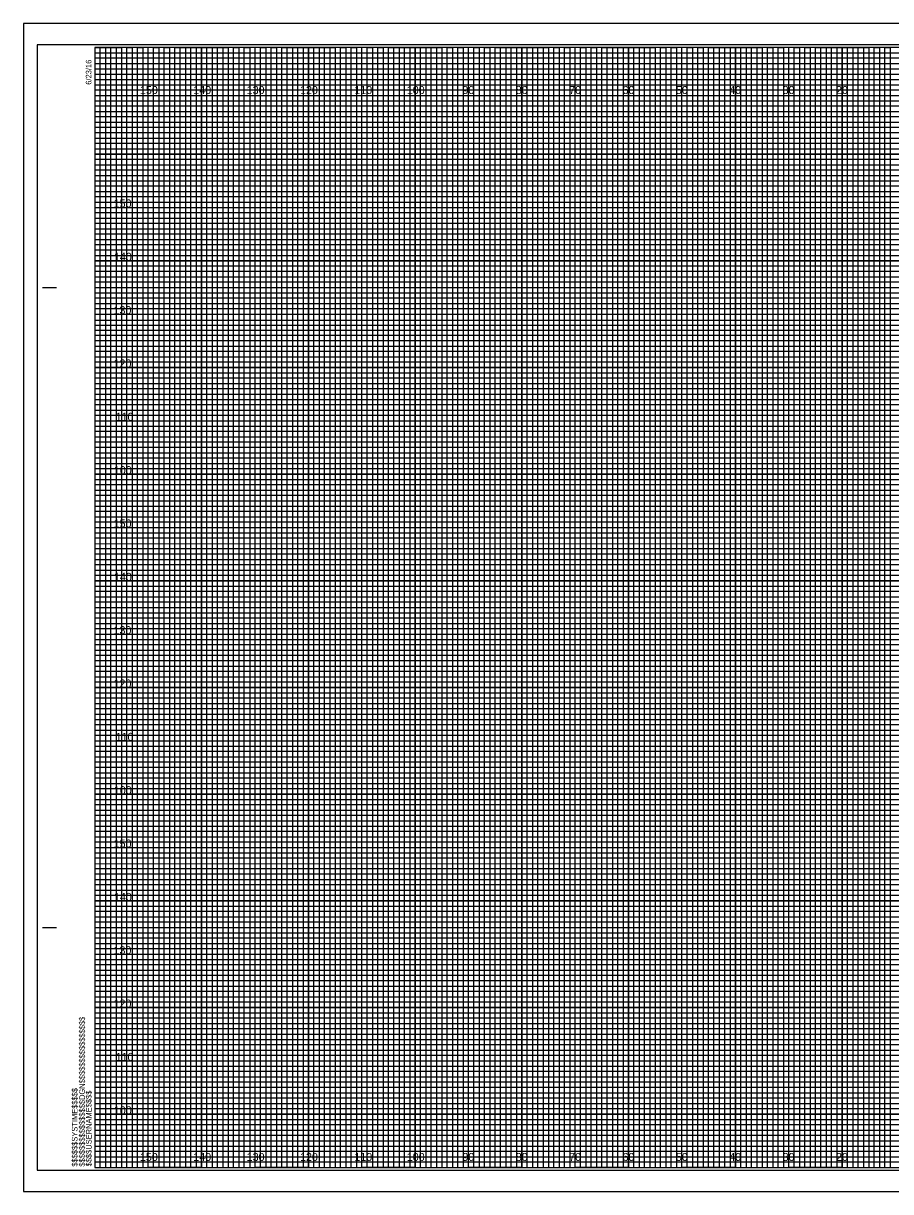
# Model space of a CAD drawing. Extents: x -13 to 323, y -5 to 2634.
# Drawn here: x -13.4 to 149.1, y 1755.5 to 1974.5 of the extents above; entities that cross this region are included whole.
import ezdxf

# ---------------------------------------------------------------- set-up
doc = ezdxf.new("R2010")
doc.units = 0
for name, color, linetype in [('Exist Cross Section Cell', 7, 'Continuous'), ('Exist XS Center Line Elevation Label', 7, 'Continuous'), ('Exist XS Ground Line', 7, 'Continuous'), ('Prop CMT Pvmt Course 1 Wedge', 7, 'Continuous'), ('Prop CMT Pvmt Course 2', 7, 'Continuous'), ('Prop CMT Pvmt Course 2 Wedge', 7, 'Continuous'), ('Prop CMT Pvmt Course 3', 7, 'Continuous'), ('Prop CMT Shld Paved Course 1', 7, 'Continuous'), ('Prop CMT Shld Paved Course 2', 7, 'Continuous'), ('Prop CMT Subgrade Earthwork', 7, 'Continuous'), ('Scratch_Level_0', 7, 'Continuous')]:
    doc.layers.add(name, color=color, linetype=linetype)

msp = doc.modelspace()

# ---------------------------------------------------------------- linework, layer by layer
at = {"layer": 'Exist XS Center Line Elevation Label'}
for points in [[(0, 1970), (5, 1970), (5, 1760), (15, 1760), (15, 1970), (25, 1970), (25, 1760), (35, 1760), (35, 1970), (45, 1970), (45, 1760), (55, 1760), (55, 1970), (65, 1970), (65, 1760), (75, 1760), (75, 1970), (85, 1970), (85, 1760), (95, 1760), (95, 1970), (105, 1970), (105, 1760), (115, 1760), (115, 1970), (125, 1970), (125, 1760), (135, 1760), (135, 1970), (145, 1970), (145, 1760), (155, 1760)], [(0, 1965), (275, 1965)], [(0, 1945), (320, 1945), (320, 1955), (0, 1955)], [(0, 1925), (320, 1925), (320, 1935), (0, 1935)], [(0, 1905), (320, 1905), (320, 1915), (0, 1915)], [(0, 1885), (320, 1885), (320, 1895), (0, 1895)], [(0, 1865), (320, 1865), (320, 1875), (0, 1875)], [(0, 1845), (320, 1845), (320, 1855), (0, 1855)], [(0, 1825), (320, 1825), (320, 1835), (0, 1835)], [(0, 1805), (320, 1805), (320, 1815), (0, 1815)], [(0, 1785), (320, 1785), (320, 1795), (0, 1795)], [(0, 1765), (320, 1765), (320, 1775), (0, 1775)]]:
    msp.add_lwpolyline(points, dxfattribs=at)
at = {"layer": 'Exist XS Ground Line'}
for p, q in [((10, 1970), (0, 1970)), ((10, 1760), (10, 1970)), ((30, 1970), (20, 1970)), ((20, 1970), (20, 1760)), ((30, 1760), (30, 1970)), ((50, 1970), (40, 1970)), ((40, 1970), (40, 1760)), ((50, 1760), (50, 1970)), ((70, 1970), (60, 1970)), ((60, 1970), (60, 1760)), ((70, 1760), (70, 1970)), ((90, 1970), (80, 1970)), ((80, 1970), (80, 1760)), ((90, 1760), (90, 1970)), ((110, 1970), (100, 1970)), ((100, 1970), (100, 1760)), ((110, 1760), (110, 1970)), ((130, 1970), (120, 1970)), ((120, 1970), (120, 1760)), ((130, 1760), (130, 1970)), ((150, 1970), (140, 1970)), ((140, 1970), (140, 1760)), ((20, 1760), (10, 1760)), ((40, 1760), (30, 1760)), ((60, 1760), (50, 1760)), ((80, 1760), (70, 1760)), ((100, 1760), (90, 1760)), ((120, 1760), (110, 1760)), ((140, 1760), (130, 1760))]:
    msp.add_line(p, q, dxfattribs=at)
for points in [[(0, 1960), (320, 1960), (320, 1950), (0, 1950)], [(0, 1940), (320, 1940), (320, 1930), (0, 1930)], [(0, 1920), (320, 1920), (320, 1910), (0, 1910)], [(0, 1900), (320, 1900), (320, 1890), (0, 1890)], [(0, 1880), (320, 1880), (320, 1870), (0, 1870)], [(0, 1860), (320, 1860), (320, 1850), (0, 1850)], [(0, 1840), (320, 1840), (320, 1830), (0, 1830)], [(0, 1820), (320, 1820), (320, 1810), (0, 1810)], [(0, 1800), (320, 1800), (320, 1790), (0, 1790)], [(0, 1780), (320, 1780), (320, 1770), (0, 1770)]]:
    msp.add_lwpolyline(points, dxfattribs=at)
at = {"layer": 'Prop CMT Pvmt Course 1 Wedge'}
for p, q in [((323.3, 1974.5), (-13.4, 1974.5)), ((-13.4, 1974.5), (-13.4, 1755.5)), ((-13.4, 1755.5), (323.3, 1755.5))]:
    msp.add_line(p, q, dxfattribs=at)
at = {"layer": 'Prop CMT Pvmt Course 2'}
msp.add_lwpolyline([(-13.4, 1755.5), (323.3, 1755.5), (323.3, 1974.5), (-13.4, 1974.5)], close=True, dxfattribs=at)
at = {"layer": 'Prop CMT Pvmt Course 3'}
msp.add_lwpolyline([(-10.8, 1759.5), (322.4, 1759.5), (322.4, 1970.5), (-10.8, 1970.5)], close=True, dxfattribs=at)
at = {"layer": 'Prop CMT Shld Paved Course 1'}
for p, q in [((-9.8, 1925), (-7.3, 1925)), ((-9.7, 1925), (-7.2, 1925)), ((-9.8, 1805), (-7.3, 1805)), ((-9.7, 1805), (-7.2, 1805)), ((0, 1760), (0, 1760)), ((0, 1760), (0, 1760)), ((0, 1760), (0, 1760)), ((0, 1760), (0, 1760)), ((0, 1760), (0, 1760)), ((0, 1760), (0, 1760)), ((0, 1760), (0, 1760))]:
    msp.add_line(p, q, dxfattribs=at)
msp.add_lwpolyline([(320, 1970), (0, 1970), (0, 1760), (320, 1760)], close=True, dxfattribs=at)
at = {"layer": 'Prop CMT Shld Paved Course 2'}
for points in [[(0, 1760), (1, 1760), (1, 1970), (2, 1970), (2, 1760)], [(2, 1760), (3, 1760), (3, 1970), (4, 1970), (4, 1760)], [(5, 1760), (6, 1760), (6, 1970), (7, 1970), (7, 1760)], [(7, 1760), (8, 1760), (8, 1970), (9, 1970), (9, 1760)], [(10, 1760), (11, 1760), (11, 1970), (12, 1970), (12, 1760)], [(12, 1760), (13, 1760), (13, 1970), (14, 1970), (14, 1760)], [(15, 1760), (16, 1760), (16, 1970), (17, 1970), (17, 1760)], [(17, 1760), (18, 1760), (18, 1970), (19, 1970), (19, 1760)], [(20, 1760), (21, 1760), (21, 1970), (22, 1970), (22, 1760)], [(22, 1760), (23, 1760), (23, 1970), (24, 1970), (24, 1760)], [(25, 1760), (26, 1760), (26, 1970), (27, 1970), (27, 1760)], [(27, 1760), (28, 1760), (28, 1970), (29, 1970), (29, 1760)], [(30, 1760), (31, 1760), (31, 1970), (32, 1970), (32, 1760)], [(32, 1760), (33, 1760), (33, 1970), (34, 1970), (34, 1760)], [(35, 1760), (36, 1760), (36, 1970), (37, 1970), (37, 1760)], [(37, 1760), (38, 1760), (38, 1970), (39, 1970), (39, 1760)], [(40, 1760), (41, 1760), (41, 1970), (42, 1970), (42, 1760)], [(42, 1760), (43, 1760), (43, 1970), (44, 1970), (44, 1760)], [(45, 1760), (46, 1760), (46, 1970), (47, 1970), (47, 1760)], [(47, 1760), (48, 1760), (48, 1970), (49, 1970), (49, 1760)], [(50, 1760), (51, 1760), (51, 1970), (52, 1970), (52, 1760)], [(52, 1760), (53, 1760), (53, 1970), (54, 1970), (54, 1760)], [(55, 1760), (56, 1760), (56, 1970), (57, 1970), (57, 1760)], [(57, 1760), (58, 1760), (58, 1970), (59, 1970), (59, 1760)], [(60, 1760), (61, 1760), (61, 1970), (62, 1970), (62, 1760)], [(62, 1760), (63, 1760), (63, 1970), (64, 1970), (64, 1760)], [(65, 1760), (66, 1760), (66, 1970), (67, 1970), (67, 1760)], [(67, 1760), (68, 1760), (68, 1970), (69, 1970), (69, 1760)], [(70, 1760), (71, 1760), (71, 1970), (72, 1970), (72, 1760)], [(72, 1760), (73, 1760), (73, 1970), (74, 1970), (74, 1760)], [(75, 1760), (76, 1760), (76, 1970), (77, 1970), (77, 1760)], [(77, 1760), (78, 1760), (78, 1970), (79, 1970), (79, 1760)], [(80, 1760), (81, 1760), (81, 1970), (82, 1970), (82, 1760)], [(82, 1760), (83, 1760), (83, 1970), (84, 1970), (84, 1760)], [(85, 1760), (86, 1760), (86, 1970), (87, 1970), (87, 1760)], [(87, 1760), (88, 1760), (88, 1970), (89, 1970), (89, 1760)], [(90, 1760), (91, 1760), (91, 1970), (92, 1970), (92, 1760)], [(92, 1760), (93, 1760), (93, 1970), (94, 1970), (94, 1760)], [(95, 1760), (96, 1760), (96, 1970), (97, 1970), (97, 1760)], [(97, 1760), (98, 1760), (98, 1970), (99, 1970), (99, 1760)], [(100, 1760), (101, 1760), (101, 1970), (102, 1970), (102, 1760)], [(102, 1760), (103, 1760), (103, 1970), (104, 1970), (104, 1760)], [(105, 1760), (106, 1760), (106, 1970), (107, 1970), (107, 1760)], [(107, 1760), (108, 1760), (108, 1970), (109, 1970), (109, 1760)], [(110, 1760), (111, 1760), (111, 1970), (112, 1970), (112, 1760)], [(112, 1760), (113, 1760), (113, 1970), (114, 1970), (114, 1760)], [(115, 1760), (116, 1760), (116, 1970), (117, 1970), (117, 1760)], [(117, 1760), (118, 1760), (118, 1970), (119, 1970), (119, 1760)], [(120, 1760), (121, 1760), (121, 1970), (122, 1970), (122, 1760)], [(122, 1760), (123, 1760), (123, 1970), (124, 1970), (124, 1760)], [(125, 1760), (126, 1760), (126, 1970), (127, 1970), (127, 1760)], [(127, 1760), (128, 1760), (128, 1970), (129, 1970), (129, 1760)], [(130, 1760), (131, 1760), (131, 1970), (132, 1970), (132, 1760)], [(132, 1760), (133, 1760), (133, 1970), (134, 1970), (134, 1760)], [(135, 1760), (136, 1760), (136, 1970), (137, 1970), (137, 1760)], [(137, 1760), (138, 1760), (138, 1970), (139, 1970), (139, 1760)], [(140, 1760), (141, 1760), (141, 1970), (142, 1970), (142, 1760)], [(142, 1760), (143, 1760), (143, 1970), (144, 1970), (144, 1760)], [(145, 1760), (146, 1760), (146, 1970), (147, 1970), (147, 1760)], [(147, 1760), (148, 1760), (148, 1970), (149, 1970), (149, 1760)]]:
    msp.add_lwpolyline(points, dxfattribs=at)
at = {"layer": 'Prop CMT Subgrade Earthwork'}
for p, q in [((10, 1760), (10, 1970)), ((20, 1760), (20, 1970)), ((30, 1760), (30, 1970)), ((40, 1760), (40, 1970)), ((50, 1760), (50, 1970)), ((60, 1760), (60, 1970)), ((70, 1760), (70, 1970)), ((80, 1760), (80, 1970)), ((90, 1760), (90, 1970)), ((100, 1760), (100, 1970)), ((110, 1760), (110, 1970)), ((120, 1760), (120, 1970)), ((130, 1760), (130, 1970)), ((140, 1760), (140, 1970)), ((0, 1960), (320, 1960)), ((0, 1950), (320, 1950)), ((0, 1940), (320, 1940)), ((0, 1930), (320, 1930)), ((0, 1920), (320, 1920)), ((0, 1910), (320, 1910)), ((0, 1900), (320, 1900)), ((0, 1890), (320, 1890)), ((0, 1880), (320, 1880)), ((0, 1870), (320, 1870)), ((0, 1860), (320, 1860)), ((0, 1850), (320, 1850)), ((0, 1840), (320, 1840)), ((0, 1830), (320, 1830)), ((0, 1820), (320, 1820)), ((0, 1810), (320, 1810)), ((0, 1800), (320, 1800)), ((0, 1790), (320, 1790)), ((0, 1780), (320, 1780)), ((0, 1770), (320, 1770))]:
    msp.add_line(p, q, dxfattribs=at)
at = {"layer": 'Scratch_Level_0'}
for p, q in [((0, 1969), (260, 1969)), ((260, 1967.98), (0, 1967.98)), ((0, 1967.98), (0, 1967)), ((0, 1967), (260, 1967)), ((260, 1965.89), (0, 1965.89)), ((0, 1965.89), (0, 1964)), ((0, 1964), (320, 1964))]:
    msp.add_line(p, q, dxfattribs=at)
for points in [[(0, 1963), (270, 1963), (320, 1963), (320, 1962), (0, 1962)], [(0, 1961), (320, 1961), (320, 1959), (0, 1959)], [(0, 1958), (320, 1958), (320, 1957), (0, 1956.98)], [(0, 1956), (320, 1956), (320, 1954), (0, 1954)], [(0, 1953), (320, 1953), (320, 1952), (0, 1952)], [(0, 1951), (320, 1951), (320, 1949), (0, 1949)], [(0, 1948), (320, 1948), (320, 1947), (0, 1947)], [(0, 1946), (320, 1946), (320, 1944), (0, 1944)], [(0, 1943), (320, 1943), (320, 1942), (0, 1942)], [(0, 1941), (320, 1941), (320, 1939), (0, 1939)], [(0, 1938), (320, 1938), (320, 1937), (0, 1937)], [(0, 1936), (320, 1936), (320, 1933.95), (320, 1933), (320, 1932), (0, 1932)], [(0, 1934), (320, 1934), (320, 1933), (0, 1933)], [(0, 1931), (320, 1931), (320, 1929), (0, 1929.03)], [(0, 1929.03), (320, 1929), (320, 1928), (0, 1928)], [(0, 1927), (320, 1927), (320, 1926), (0, 1926)], [(0, 1924), (320, 1924), (320, 1923), (0, 1923)], [(0, 1922), (320, 1922), (320, 1921), (0, 1921)], [(-0.07, 1918.89), (320, 1918.89), (320, 1917.88), (-0.07, 1917.88)], [(0, 1917), (320, 1917), (320, 1916), (0, 1916)], [(0, 1914), (320, 1914), (320, 1913), (0, 1913)], [(0, 1912), (320, 1912), (320, 1911), (0, 1911)], [(0, 1909), (320, 1909), (320, 1908), (0, 1908)], [(0, 1907), (320, 1907), (320, 1906), (0, 1906)], [(0, 1904), (320, 1904), (320, 1903), (0, 1903)], [(0, 1902), (320, 1902), (320, 1901), (0, 1901)], [(0, 1899), (320, 1899), (319.99, 1897.98), (0, 1898)], [(0, 1897), (320, 1897), (320, 1896), (0, 1896)], [(0, 1894), (320, 1894), (320, 1893), (0, 1893)], [(0, 1892), (320, 1892), (320, 1891), (0, 1891)], [(0, 1889), (320, 1889), (320, 1888), (0, 1888)], [(0, 1887), (320, 1887), (320, 1886), (0, 1886)], [(0, 1884), (320, 1884), (320, 1883), (0, 1883)], [(0, 1882), (320, 1882), (320, 1881), (0, 1881)], [(0, 1879), (320, 1879), (320, 1878), (0, 1878)], [(0, 1876.99), (320.07, 1876.91), (320, 1876), (0, 1876)], [(0, 1874), (320, 1874), (320, 1873), (0, 1873)], [(0, 1872), (320, 1872), (320, 1871), (0, 1871)], [(0, 1869), (320, 1869), (320, 1868), (0, 1868)], [(0, 1867), (320, 1867), (320, 1866), (0, 1866)], [(0, 1864), (320, 1864), (320, 1863), (0, 1863)], [(0, 1862), (320, 1862), (320, 1861), (0, 1861)], [(0, 1859), (320, 1859), (320, 1858), (0, 1858)], [(0, 1857), (320, 1857), (320, 1856), (0, 1856)], [(0, 1854), (320, 1854), (320, 1853), (0, 1853)], [(0, 1852), (320, 1852), (320, 1851), (0, 1851)], [(0, 1849), (320, 1849), (320, 1848), (0, 1848)], [(0, 1847), (320, 1847), (320, 1846), (0, 1846)], [(0, 1844), (320, 1844), (320, 1843), (0, 1843)], [(0, 1842), (320, 1842), (320, 1841), (0, 1841)], [(0, 1839), (320, 1839), (319.99, 1837.98), (0, 1838)], [(0, 1837), (320, 1837), (320, 1836), (0, 1836)], [(0, 1834), (320, 1834), (320, 1833), (0, 1833)], [(0, 1832), (320, 1832), (320, 1831), (0, 1831)], [(0, 1829), (320, 1829), (320, 1828), (0, 1828)], [(0, 1827), (320, 1827), (320, 1826), (0, 1826)], [(0, 1824), (320, 1824), (320, 1823), (0, 1823)], [(0, 1822), (320, 1822), (320, 1821), (0, 1821)], [(0, 1819), (320, 1819), (320, 1818), (0, 1818)], [(0, 1816.99), (320.07, 1816.91), (320, 1816), (0, 1816)], [(0, 1814), (320, 1814), (320, 1813), (0, 1813)], [(0, 1812), (320, 1812), (320, 1811), (0, 1811)], [(0, 1809), (320, 1809), (320, 1808), (0, 1808)], [(0, 1807), (320, 1807), (320, 1806), (0, 1806)], [(0, 1804), (320, 1804), (320, 1803), (0, 1803)], [(0, 1802), (320, 1802), (320, 1801), (0, 1801)], [(0, 1799), (320, 1799), (320, 1798), (0, 1798)], [(0, 1797), (320, 1797), (320, 1796), (0, 1796)], [(0, 1794), (320, 1794), (320, 1793), (0, 1793)], [(0, 1792), (320, 1792), (320, 1791), (0, 1791)], [(0, 1789), (320, 1789), (320, 1788), (0, 1788)], [(0, 1787), (320, 1787), (320, 1786), (0, 1786)], [(0, 1784), (320, 1784), (320, 1783), (0, 1783)], [(0, 1782), (320, 1782), (320, 1781), (0, 1781)], [(0, 1779), (320, 1779), (320, 1778), (0, 1778)], [(0, 1777), (320, 1777), (320, 1776), (0, 1776)], [(0, 1774), (320, 1774), (320, 1773), (0, 1773)], [(0, 1772), (320, 1772), (320, 1771), (0, 1771)], [(0, 1769), (320, 1769), (320, 1768), (0, 1768)], [(0, 1767), (320, 1767), (320, 1766), (0, 1766)], [(0, 1764), (320, 1764), (320, 1763), (0, 1763)], [(0, 1762), (320, 1762), (320, 1761), (0, 1761)]]:
    msp.add_lwpolyline(points, dxfattribs=at)

# ---------------------------------------------------------------- texts
at = {"layer": 'Exist Cross Section Cell'}
for s, p in [('150', (8.44, 1961.25)), ('140', (18.44, 1961.25)), ('130', (28.44, 1961.25)), ('120', (38.44, 1961.25)), ('110', (48.62, 1961.25)), ('100', (58.44, 1961.25)), ('90', (68.86, 1961.25)), ('80', (78.86, 1961.25)), ('70', (88.86, 1961.25)), ('60', (98.86, 1961.25)), ('50', (108.86, 1961.25)), ('40', (118.86, 1961.25)), ('30', (128.86, 1961.25)), ('20', (138.86, 1961.25)), ('150', (8.44, 1761.25)), ('140', (18.44, 1761.25)), ('130', (28.44, 1761.25)), ('120', (38.44, 1761.25)), ('110', (48.62, 1761.25)), ('100', (58.44, 1761.25)), ('90', (68.86, 1761.25)), ('80', (78.86, 1761.25)), ('70', (88.86, 1761.25)), ('60', (98.86, 1761.25)), ('50', (108.86, 1761.25)), ('40', (118.86, 1761.25)), ('30', (128.86, 1761.25)), ('20', (138.86, 1761.25))]:
    msp.add_text(s, height=1.5, dxfattribs=at).set_placement(p)
at = {"layer": 'Prop CMT Pvmt Course 2 Wedge'}
for s, p in [('150', (3.52, 1940)), ('140', (3.57, 1930)), ('130', (3.49, 1920)), ('120', (3.5, 1910)), ('110', (3.88, 1900)), ('100', (3.55, 1890)), ('150', (3.52, 1880)), ('140', (3.57, 1870)), ('130', (3.49, 1860)), ('120', (3.5, 1850)), ('110', (3.88, 1840)), ('100', (3.55, 1830)), ('150', (3.52, 1820)), ('140', (3.57, 1810)), ('130', (3.49, 1800)), ('120', (3.5, 1790)), ('110', (3.88, 1780)), ('100', (3.55, 1770))]:
    msp.add_text(s, height=1.5, dxfattribs=at).set_placement(p)
at = {"layer": 'Prop CMT Shld Paved Course 1'}
for s, p in [('6/23/16', (-0.65, 1963)), ('$$$$$$$$$$$$$$$$DGN$$$$$$$$$$$$$$$$', (-1.88, 1760.18)), ('$$$$$$SYSTIME$$$$$', (-3.26, 1760.18)), ('$$$$USERNAME$$$$', (-0.62, 1760.23))]:
    msp.add_text(s, height=1.05, rotation=90, dxfattribs=at).set_placement(p)

doc.saveas('drawing.dxf')
